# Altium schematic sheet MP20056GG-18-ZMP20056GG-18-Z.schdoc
size 127 x 101 mm
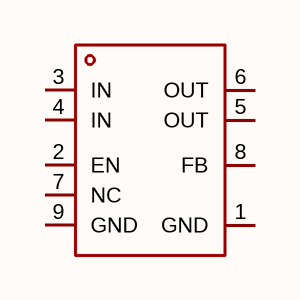
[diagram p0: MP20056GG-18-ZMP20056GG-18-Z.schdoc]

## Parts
U?  mp20056gg-18-z  [QFN-8_L2.0-W2.0-P0.50-BL-EP]  (value not drawn)

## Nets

Not connected (* = marked no-connect by the designer): U? 1(GND) 2(EN) 3(IN) 4(IN) 5(OUT) 6(OUT) 7(NC) 8(FB) 9(GND)

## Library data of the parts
U? = mp20056gg-18-z: 输出极性:正极;工作电压:5.5V;输出电压:1.8V；800mV~5V;输出电流:250mA;电源纹波抑制比(PSRR):63dB;输出类型:固定；可调;; Manufacturer: MPS(芯源); AddInBom: yes; ModelId: 86202c8e5c19411b879329bf817ae476; ModelTransform: 79.527,79.1337,0,90,0,0,0.005,0,0; Output Configuration: 正极; Voltage - Supply: 5.5V; Output Current: 250mA; Power Supply Rejection Ratio (PSRR): 63dB; standby current: 150uA; Noise: 20uVrms; Output Type: 固定；可调; Number of Outputs: 1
